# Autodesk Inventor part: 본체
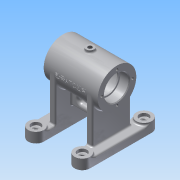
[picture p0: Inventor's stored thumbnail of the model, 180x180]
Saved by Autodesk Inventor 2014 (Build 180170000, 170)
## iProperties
Created: 2015-11
Part Number: 본체
Material: 알루미늄 6061
Document SubType Name: Modeling
Designer: 103-25
Density: 2.71 g/cm^3
Appearance: 알루미늄 - 평지
Mass: 358.579 g
Surface Area: 458.836 cm^2
Volume: 132.317 cm^3
Author: 103-25
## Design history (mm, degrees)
sketch "스케치1"
  geometry: L1 (-40, 40)-(-40, -40); L2 (-20, 40)-(-20, -40); A1 r 10 centre (-30, 40) between (-40, 40) and (-20, 40); A2 r 10 centre (-30, -40) between (-40, -40) and (-20, -40); 2 further points
  constraints: 4 end point, 4 point on circle, 4 tangent, 2 centre point, 1 equal radius, 1 horizontal alignment, 1 midpoint, 1 vertical alignment
  dimensions: "d3" = 20 diameter of A1; "d4" = 80 distance of A2.centre A1.centre; "d6" = 40 distance from line of point (0, 0) L1
extrude "돌출1" new body sketch "스케치1" distance "d7" = 10; taper "d8" = 0 deg
extrude "돌출2" join sketch "스케치1" distance "d9" = 13; taper "d10" = 0 deg
node "작업 평면2"
sketch "스케치2"
  geometry: L1 (40, 0)-(-40, 0) reference; C1 r 25 at (0, 68); 2 further points
  constraints: 1 centre point, 1 midpoint, 1 vertical alignment
  dimensions: "d12" = 50 diameter of C1; "d13" = 68 distance from line of L1 C1.centre
extrude "돌출3" join sketch "스케치2" stored distance "d14" = 70; taper "d15" = 0 deg
sketch "스케치3"
  geometry: L1 (-10, 0)-(-10, 80) reference; L2 (-68, 15)-(-10, 15); L3 (-68, 65)-(-10, 65); L4 (-10, 15)-(-10, 65); L5 (-68, 15)-(-68, 65); C1 r 25 at (-68, 40) reference; 1 further point
  constraints: 8 end point, 2 perpendicular, 2 point on line, 1 collinear, 1 midpoint, 1 parallel, 1 tangent
  dimensions: "d16" = 50 distance between parallel lines of L3 L2
extrude "돌출4" join sketch "스케치3" distance "d17" = 8; taper "d18" = 0 deg
node "작업 평면7"
sketch "스케치9"
  geometry: L1 (-35, 43)-(-35, 93) reference; L2 (-35, 93)-(35, 93) reference; L3 (35, 93)-(35, 43) reference; L4 (35, 43)-(28, 43) reference; L5 (28, 43)-(28, 10) reference; L6 (28, 10)-(40, 10) reference; L7 (40, 10)-(40, 0) reference; L8 (40, 0)-(20, 0) reference; L9 (20, 0)-(20, 43) reference; L10 (20, 43)-(-20, 43) reference; L11 (-20, 43)-(-20, 0) reference; L12 (-20, 0)-(-40, 0) reference; L13 (-40, 0)-(-40, 10) reference; L14 (-40, 10)-(-28, 10) reference; L15 (-28, 10)-(-28, 43) reference; L16 (-28, 43)-(-35, 43) reference; L17 (-20, 23)-(20, 23); L18 (-8, 36.5)-(8, 36.5); L19 (8, 29.5)-(-8, 29.5); L20 (-20, 23)-(-20, 53); L21 (-20, 53)-(20, 53); L22 (20, 53)-(20, 23); A1 r 3.5 centre (8, 33) between (8, 29.5) and (8, 36.5); A2 r 3.5 centre (-8, 33) between (-8, 36.5) and (-8, 29.5); 2 further points
  constraints: 12 end point, 4 point on circle, 4 tangent, 3 point on line, 2 centre point, 2 perpendicular, 1 collinear, 1 horizontal, 1 midpoint, 1 parallel, 1 vertical alignment
  dimensions: "d88" = 20 distance between parallel lines of L17 L10; "d89" = 23 dimension on A1 A2; "d90" = 33 distance from line of L8 A1.centre; "d91" = 3.5 radius of A1; "d123" = 30 distance between parallel lines of L17 L21
extrude "돌출7" join sketch "스케치9" stored distance "d92" = 8; taper "d93" = 0 deg
node "작업 평면3"
sketch "스케치4"
  geometry: C1 r 5 at (-30, 40); 1 further point
  constraints: 1 centre point, 1 coincident
  dimensions: "d20" = 10 diameter of C1
extrude "돌출5" join sketch "스케치4" stored distance "d21" = 10 (= d20); taper "d22" = 0 deg
node "작업 평면4"
sketch "스케치5"
  geometry: L1 (-68, 40)-(-43.751, 54); 3 further points
  constraints: 2 end point, 2 horizontal alignment, 1 coincident, 1 other
  dimensions: "d25" = 30 deg dimension on L1.start L1.end point (-43, 40); "d26" = 28 distance of L1.start L1.end
  node "투영된 루프1"
node "작업 평면6"
sketch "스케치7"
  geometry: C1 r 6 at (0, 0); 2 further points
  constraints: 1 centre point, 1 coincident
  dimensions: "d27" = 12 diameter of C1
extrude "돌출6" join sketch "스케치7" stored distance "d28" = 8; taper "d29" = 0 deg
hole "구멍1" diameter "d32" = 5.188; stored, may be unused: countersink angle "d36" = 90 deg, drill point angle "d38" = 118 deg; dims "d30" = 10, "d31" = 10, "d33" = 6, "d34" = 4, "d35" = 2, "d37" = 28
hole "구멍2" diameter "d41" = 5.188; stored, may be unused: countersink angle "d45" = 90 deg, drill point angle "d47" = 118 deg; dims "d39" = 10, "d40" = 10, "d42" = 6, "d43" = 4, "d44" = 2, "d46" = 28
hole "구멍3" diameter "d50" = 28; stored, may be unused: countersink angle "d54" = 90 deg, drill point angle "d56" = 0 deg; dims "d48" = 10, "d49" = 10, "d51" = 6, "d52" = 32, "d53" = 12, "d55" = 14
hole "구멍4" diameter "d59" = 28; stored, may be unused: countersink angle "d63" = 90 deg, drill point angle "d65" = 0 deg; dims "d57" = 10, "d58" = 10, "d60" = 6, "d61" = 32, "d62" = 12, "d64" = 14
hole "구멍5" diameter "d68" = 42; stored, may be unused: countersink angle "d72" = 90 deg, drill point angle "d74" = 0 deg; dims "d66" = 10, "d67" = 10, "d69" = 6, "d70" = 32, "d71" = 12, "d73" = 42
sketch "스케치8"
  geometry: C1 r 16 at (0, 0) reference; 2 further points
  constraints: 1 vertical alignment
  dimensions: "d75" = 20 distance of C1.centre point (0, 20)
hole "구멍6" sketch "스케치8" at (0, 20) diameter "d76" = 3.242; stored, may be unused: countersink angle "d80" = 90 deg, drill point angle "d82" = 118 deg; dims "d77" = 8, "d78" = 32, "d79" = 12, "d81" = 10
sketch "스케치10"
  geometry: C1 r 10 at (0, 0) reference; C2 r 10 at (0, 80) reference; C3 r 10 at (60, 80) reference; C4 r 10 at (60, 0) reference; 5 further points
  constraints: 4 coincident
hole "구멍7" sketch "스케치10" at (0, 80), (60, 80), (60, 0), (0, 0) diameter "d94" = 6; stored, may be unused: countersink angle "d98" = 90 deg, drill point angle "d100" = 118 deg; dims "d95" = 8, "d96" = 12, "d97" = 4, "d99" = 10
node "작업 평면8"
sketch "스케치11"
  geometry: L1 (-35, 25)-(35, 25) reference; L2 (-35, 25)-(-35, -25) reference; 2 further points
  constraints: 1 other
  dimensions: "d101" = 35 distance from line of L2 point (0, 0); "d102" = 25 distance from line of L1 point (0, 0)
feature "엠보싱1" sketch "스케치11" dims "d103" = 0.5, "d104" = 0
chamfer "모따기1" distance "d105" = 1; stored, may be unused: second distance "d106" = 2, angle "d107" = 45 deg
fillet "모깎기1" dims "d108" = 0.3, "d109" = 3.5
fillet "모깎기4" dims "d112" = 2
fillet "모깎기5" dims "d113" = 2
fillet "모깎기6" dims "d114" = 2
fillet "모깎기7" dims "d115" = 2
fillet "모깎기8" dims "d116" = 2
fillet "모깎기10" dims "d118" = 2
fillet "모깎기11" dims "d119" = 3
fillet "모깎기12" dims "d120" = 2
fillet "모깎기14" dims "d122" = 2
fillet "모깎기15" dims "d124" = 2
fillet "모깎기16" dims "d125" = 2
node "솔리드1"
mirror "대칭1"
mirror "대칭2"
pattern_circular "원형 패턴1" dims angle "d84" = 360 deg
mirror "대칭3"
node "작업 평면1"
node "절단 모서리 투영1"
other parameters: "d11" = 0, "d19" = -96, "d86" = 0
